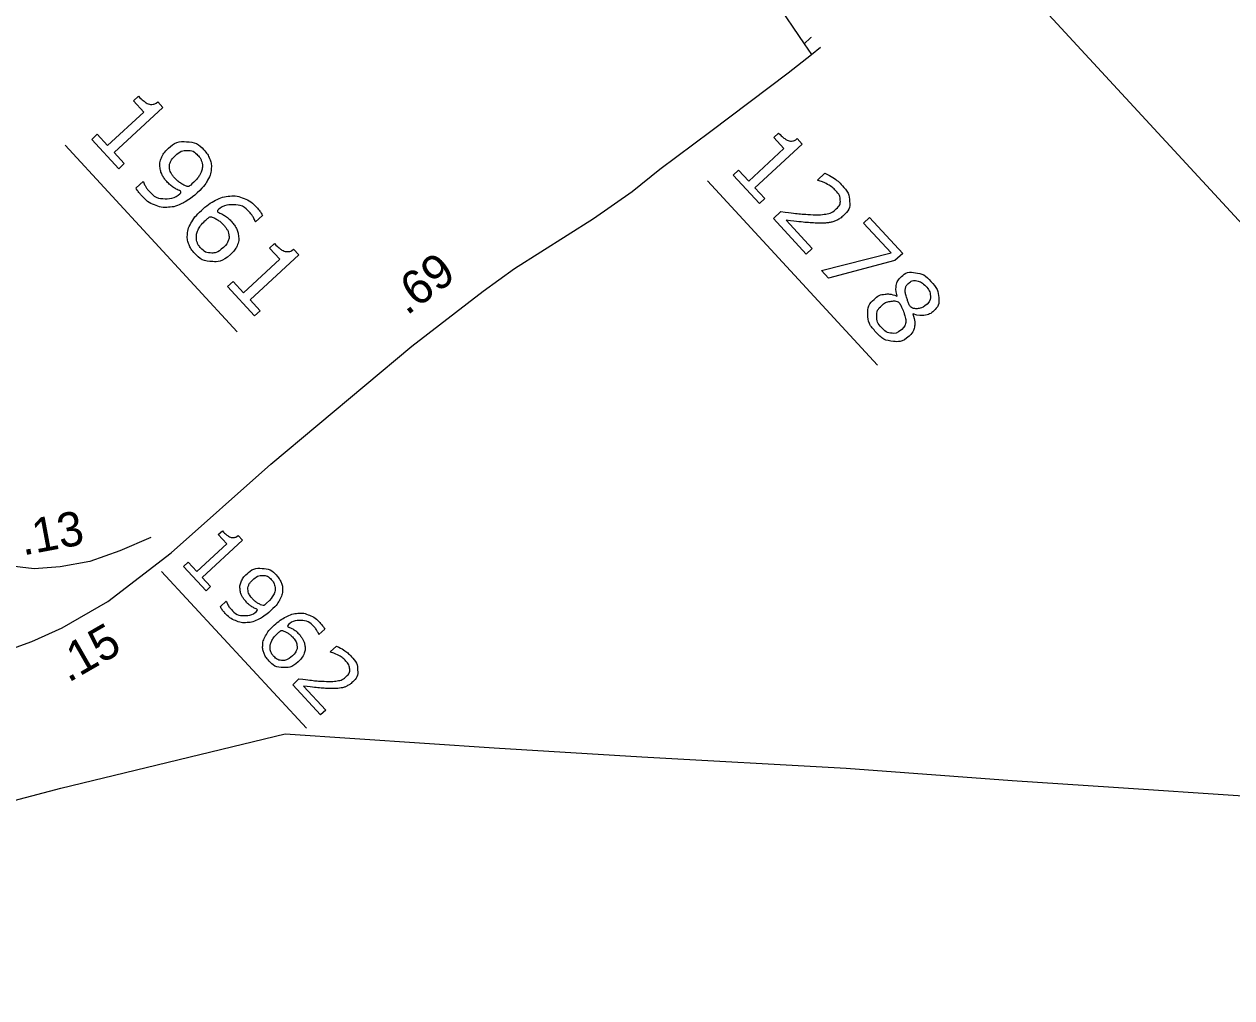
# Model space of a CAD drawing. Extents: x 1695041 to 1706254, y 786537 to 798223.
# Drawn here: x 1703431.2 to 1703634.1, y 796970.9 to 797134.4 of the extents above; entities that cross this region are included whole.
import ezdxf

# ---------------------------------------------------------------- set-up
doc = ezdxf.new("R2010")
doc.units = 0
for name, color, linetype in [('Default', 7, 'Continuous'), ('Old_Level_32', 7, 'Continuous'), ('Sheet Title CELL', 7, 'Continuous')]:
    doc.layers.add(name, color=color, linetype=linetype)

msp = doc.modelspace()

# ---------------------------------------------------------------- linework, layer by layer
at = {"layer": 'Default'}
for p, q in [((1703835.77, 796884.26), (1703207.65, 797564.73)), ((1703438.09, 797114.05), (1703467.03, 797082.7)), ((1703546.02, 797108.1), (1703574.62, 797077.11)), ((1703454.31, 797042.48), (1703478.63, 797016.14))]:
    msp.add_line(p, q, dxfattribs=at)
for points in [[(1703563.46, 797132.18), (1703563.36, 797132.1), (1703562.3, 797131.12)], [(1703563.52, 797129.33), (1703565, 797130.52)], [(1703447.11, 797110.12), (1703442.57, 797115.04), (1703443.5, 797115.9), (1703445.24, 797114), (1703451.34, 797119.63), (1703449.59, 797121.52), (1703450.42, 797122.29)], [(1703453.65, 797121.34), (1703454.53, 797120.4), (1703446.33, 797112.83), (1703448.04, 797110.97), (1703447.11, 797110.12)], [(1703554.77, 797104.28), (1703550.36, 797109.05), (1703551.27, 797109.89), (1703552.96, 797108.05), (1703558.88, 797113.51), (1703557.18, 797115.34), (1703557.99, 797116.09)], [(1703561.12, 797115.17), (1703561.97, 797114.25), (1703554.01, 797106.91), (1703555.67, 797105.11), (1703554.77, 797104.28)], [(1703450.02, 797106.89), (1703451.2, 797107.97), (1703451.25, 797107.91)], [(1703564.58, 797108.14), (1703564.52, 797108.2), (1703565.76, 797109.35)], [(1703471.25, 797102.28), (1703470.07, 797101.2), (1703470.02, 797101.26)], [(1703562.62, 797095.77), (1703557.1, 797101.75), (1703558.35, 797102.91)], [(1703559.26, 797101.47), (1703563.65, 797096.72), (1703562.62, 797095.77)], [(1703577.53, 797094.68), (1703566.34, 797091.74), (1703565.17, 797093.01), (1703576.87, 797095.97), (1703572.24, 797100.98), (1703573.28, 797101.94), (1703578.85, 797095.9), (1703577.53, 797094.68)], [(1703469.94, 797085.38), (1703465.4, 797090.31), (1703466.33, 797091.16), (1703468.07, 797089.27), (1703474.17, 797094.9), (1703472.42, 797096.79), (1703473.25, 797097.56)], [(1703476.48, 797096.61), (1703477.35, 797095.66), (1703469.16, 797088.1), (1703470.87, 797086.24), (1703469.94, 797085.38)], [(1703577.87, 797088.71), (1703577.91, 797088.74)], [(1703580.57, 797085.76), (1703580.53, 797085.73)], [(1703461.77, 797039.23), (1703458.01, 797043.3), (1703458.78, 797044.01), (1703460.23, 797042.44), (1703465.26, 797047.09), (1703463.82, 797048.66), (1703464.51, 797049.29)], [(1703467.17, 797048.51), (1703467.9, 797047.73), (1703461.12, 797041.47), (1703462.54, 797039.94), (1703461.77, 797039.23)], [(1703464.18, 797036.56), (1703465.15, 797037.46), (1703465.19, 797037.41)], [(1703481.71, 797032.75), (1703480.74, 797031.86), (1703480.7, 797031.91)], [(1703482.7, 797028.89), (1703482.65, 797028.95), (1703483.71, 797029.92)], [(1703481.03, 797018.36), (1703476.33, 797023.45), (1703477.39, 797024.44)], [(1703478.17, 797023.21), (1703481.9, 797019.16), (1703481.03, 797018.36)], [(1703291.97, 797015.19), (1703324.69, 797005.69), (1703340.9, 797002.01), (1703346.94, 797000.11), (1703357.14, 796996.22), (1703368.85, 796991.59), (1703392.4, 796995.22), (1703415.7, 797000.36), (1703437.39, 797006.05), (1703475.08, 797015.18), (1703510.21, 797012.82), (1703534.98, 797011.35), (1703569.35, 797009.42), (1703597.22, 797007.38), (1703614.23, 797006.26), (1703657.83, 797003.31), (1703684.12, 797001.47)]]:
    msp.add_lwpolyline(points, dxfattribs=at)
for points in [[(1703450.42, 797122.29), (1703450.78, 797121.91), (1703451.25, 797121.53), (1703451.72, 797121.14), (1703452.05, 797121.03), (1703452.46, 797120.89), (1703452.85, 797120.95), (1703453.23, 797121), (1703453.65, 797121.34)], [(1703557.99, 797116.09), (1703558.33, 797115.72), (1703558.79, 797115.35), (1703559.24, 797114.98), (1703559.56, 797114.87), (1703559.96, 797114.73), (1703560.34, 797114.79), (1703560.71, 797114.84), (1703561.12, 797115.17)], [(1703451.25, 797107.91), (1703451.32, 797107.65), (1703451.54, 797107.25), (1703451.75, 797106.85), (1703452.12, 797106.45), (1703453.37, 797105.1), (1703454.88, 797105.08), (1703456.4, 797105.06), (1703457.93, 797106.25), (1703457.07, 797106.51), (1703456.46, 797106.87), (1703455.85, 797107.24), (1703455.3, 797107.83), (1703454.79, 797108.39), (1703454.48, 797108.94), (1703454.17, 797109.5), (1703454.06, 797110.25), (1703453.94, 797111.13), (1703454.27, 797111.94), (1703454.59, 797112.74), (1703455.39, 797113.48), (1703456.79, 797114.76), (1703458.51, 797114.66), (1703460.23, 797114.55), (1703461.44, 797113.23), (1703462.05, 797112.57), (1703462.37, 797111.82), (1703462.68, 797111.07), (1703462.66, 797110.27), (1703462.63, 797109.28), (1703462.09, 797108.26), (1703461.55, 797107.24), (1703460.29, 797106.07)], [(1703459.41, 797107.56), (1703460.36, 797108.44), (1703460.75, 797109.16), (1703461.15, 797109.89), (1703461.15, 797110.52), (1703461.16, 797111.06), (1703460.98, 797111.5), (1703460.79, 797111.94), (1703460.44, 797112.32), (1703459.63, 797113.2), (1703458.61, 797113.2), (1703457.59, 797113.21), (1703456.59, 797112.29), (1703456.01, 797111.75), (1703455.79, 797111.25), (1703455.58, 797110.74), (1703455.66, 797110.1), (1703455.73, 797109.65), (1703455.97, 797109.26), (1703456.21, 797108.87), (1703456.58, 797108.47), (1703457.02, 797108), (1703457.6, 797107.63), (1703458.18, 797107.26), (1703458.81, 797107.06), (1703458.95, 797107.17), (1703459.08, 797107.27), (1703459.22, 797107.38), (1703459.41, 797107.56)], [(1703558.35, 797102.91), (1703559.46, 797102.78), (1703560.57, 797102.64), (1703561.68, 797102.51), (1703562.71, 797102.45), (1703564.86, 797102.33), (1703565.9, 797102.51), (1703566.94, 797102.68), (1703567.69, 797103.38), (1703568.38, 797104.01), (1703568.35, 797104.82), (1703568.32, 797105.64), (1703567.56, 797106.45), (1703567.06, 797106.99), (1703566.29, 797107.45), (1703565.52, 797107.9), (1703564.58, 797108.14)], [(1703565.76, 797109.35), (1703566.36, 797109.12), (1703567.18, 797108.57), (1703568, 797108.03), (1703568.61, 797107.37), (1703569.86, 797106.01), (1703569.92, 797104.64), (1703569.98, 797103.26), (1703568.86, 797102.23), (1703568.36, 797101.76), (1703567.8, 797101.49), (1703567.25, 797101.21), (1703566.63, 797101.1), (1703566.05, 797100.99), (1703565.41, 797100.98), (1703564.76, 797100.96), (1703563.92, 797101.01), (1703562.71, 797101.07), (1703561.51, 797101.21), (1703560.3, 797101.34), (1703559.26, 797101.47)], [(1703460.29, 797106.07), (1703459.1, 797104.97), (1703457.87, 797104.35), (1703456.65, 797103.72), (1703455.46, 797103.64), (1703454.25, 797103.55), (1703453.09, 797104.04), (1703451.94, 797104.53), (1703450.9, 797105.66), (1703450.61, 797105.97), (1703450.38, 797106.29), (1703450.15, 797106.6), (1703450.02, 797106.89)], [(1703465.88, 797095.7), (1703464.5, 797094.41), (1703462.78, 797094.52), (1703461.06, 797094.62), (1703459.83, 797095.95), (1703459.21, 797096.62), (1703458.91, 797097.36), (1703458.61, 797098.1), (1703458.63, 797098.9), (1703458.66, 797099.9), (1703459.23, 797100.95), (1703459.81, 797102.01), (1703460.99, 797103.1), (1703462.2, 797104.22), (1703463.37, 797104.82), (1703464.55, 797105.42), (1703465.8, 797105.53), (1703466.98, 797105.62), (1703468.16, 797105.13), (1703469.33, 797104.64), (1703470.37, 797103.51), (1703470.7, 797103.15), (1703470.9, 797102.88), (1703471.09, 797102.61), (1703471.25, 797102.28)], [(1703470.02, 797101.26), (1703469.95, 797101.52), (1703469.72, 797101.94), (1703469.48, 797102.36), (1703469.15, 797102.72), (1703467.94, 797104.03), (1703466.4, 797104.06), (1703464.85, 797104.08), (1703463.34, 797102.92), (1703464.12, 797102.69), (1703464.74, 797102.34), (1703465.36, 797102), (1703465.97, 797101.34), (1703466.5, 797100.76), (1703466.8, 797100.22), (1703467.1, 797099.68), (1703467.21, 797098.92), (1703467.33, 797098.04), (1703467.01, 797097.24), (1703466.7, 797096.45), (1703465.88, 797095.7)], [(1703464.68, 797096.89), (1703465.25, 797097.41), (1703465.47, 797097.92), (1703465.69, 797098.43), (1703465.61, 797099.07), (1703465.54, 797099.53), (1703465.29, 797099.93), (1703465.03, 797100.33), (1703464.69, 797100.7), (1703464.21, 797101.22), (1703463.68, 797101.55), (1703463.15, 797101.88), (1703462.46, 797102.11), (1703462.31, 797102), (1703462.18, 797101.89), (1703462.05, 797101.78), (1703461.86, 797101.61), (1703460.9, 797100.72), (1703460.52, 797100.01), (1703460.15, 797099.29), (1703460.14, 797098.65), (1703460.14, 797098.12), (1703460.31, 797097.68), (1703460.49, 797097.24), (1703460.84, 797096.85), (1703461.66, 797095.97), (1703462.67, 797095.96), (1703463.67, 797095.95), (1703464.68, 797096.89)], [(1703473.25, 797097.56), (1703473.61, 797097.17), (1703474.08, 797096.79), (1703474.55, 797096.41), (1703474.88, 797096.3), (1703475.29, 797096.16), (1703475.68, 797096.21), (1703476.06, 797096.27), (1703476.48, 797096.61)], [(1703577.91, 797088.74), (1703577.63, 797089.8), (1703577.77, 797090.56), (1703577.9, 797091.32), (1703578.58, 797091.94), (1703579.57, 797092.86), (1703580.99, 797092.65), (1703582.41, 797092.45), (1703583.58, 797091.18), (1703584.8, 797089.86), (1703584.89, 797088.49), (1703584.99, 797087.11), (1703584.01, 797086.21), (1703583.41, 797085.66), (1703582.49, 797085.5), (1703581.56, 797085.34), (1703580.57, 797085.76)], [(1703582.92, 797087.37), (1703583.55, 797087.95), (1703583.48, 797088.79), (1703583.4, 797089.63), (1703582.7, 797090.39), (1703582.01, 797091.13), (1703581.21, 797091.28), (1703580.42, 797091.43), (1703579.81, 797090.88), (1703579.38, 797090.48), (1703579.3, 797089.95), (1703579.21, 797089.43), (1703579.41, 797088.72), (1703579.51, 797088.4), (1703579.72, 797087.83), (1703579.93, 797087.26), (1703580.18, 797086.76), (1703581.11, 797086.53), (1703581.74, 797086.7), (1703582.37, 797086.86), (1703582.92, 797087.37)], [(1703579.91, 797081.98), (1703578.76, 797080.93), (1703577.18, 797081.12), (1703575.6, 797081.31), (1703574.35, 797082.67), (1703573.02, 797084.1), (1703572.98, 797085.64), (1703572.94, 797087.17), (1703574.09, 797088.24), (1703574.83, 797088.92), (1703575.82, 797089.04), (1703576.81, 797089.16), (1703577.87, 797088.71)], [(1703578.67, 797083.1), (1703579.22, 797083.6), (1703579.32, 797084.15), (1703579.43, 797084.69), (1703579.12, 797085.7), (1703578.99, 797086.1), (1703578.79, 797086.53), (1703578.6, 797086.97), (1703578.29, 797087.71), (1703577.51, 797087.97), (1703576.72, 797087.83), (1703575.92, 797087.7), (1703575.29, 797087.12), (1703574.49, 797086.38), (1703574.48, 797085.35), (1703574.47, 797084.31), (1703575.25, 797083.47), (1703576.05, 797082.6), (1703576.97, 797082.49), (1703577.9, 797082.38), (1703578.67, 797083.1)], [(1703580.53, 797085.73), (1703580.95, 797084.57), (1703580.83, 797083.65), (1703580.71, 797082.73), (1703579.91, 797081.98)], [(1703464.51, 797049.29), (1703464.8, 797048.97), (1703465.19, 797048.66), (1703465.58, 797048.34), (1703465.85, 797048.25), (1703466.19, 797048.13), (1703466.51, 797048.18), (1703466.83, 797048.23), (1703467.17, 797048.51)], [(1703465.19, 797037.41), (1703465.25, 797037.19), (1703465.43, 797036.86), (1703465.61, 797036.53), (1703465.91, 797036.2), (1703466.94, 797035.08), (1703468.19, 797035.07), (1703469.44, 797035.05), (1703470.71, 797036.04), (1703470, 797036.25), (1703469.49, 797036.55), (1703468.99, 797036.85), (1703468.54, 797037.34), (1703468.11, 797037.8), (1703467.86, 797038.26), (1703467.6, 797038.72), (1703467.51, 797039.34), (1703467.41, 797040.07), (1703467.68, 797040.73), (1703467.95, 797041.4), (1703468.61, 797042.01), (1703469.76, 797043.07), (1703471.19, 797042.98), (1703472.61, 797042.89), (1703473.61, 797041.8), (1703474.12, 797041.26), (1703474.38, 797040.64), (1703474.64, 797040.01), (1703474.62, 797039.35), (1703474.6, 797038.54), (1703474.15, 797037.7), (1703473.71, 797036.85), (1703472.66, 797035.89)], [(1703471.93, 797037.12), (1703472.72, 797037.84), (1703473.04, 797038.44), (1703473.37, 797039.04), (1703473.37, 797039.56), (1703473.38, 797040.01), (1703473.23, 797040.37), (1703473.07, 797040.74), (1703472.78, 797041.05), (1703472.11, 797041.78), (1703471.27, 797041.78), (1703470.42, 797041.78), (1703469.6, 797041.02), (1703469.12, 797040.58), (1703468.94, 797040.16), (1703468.77, 797039.75), (1703468.84, 797039.22), (1703468.89, 797038.84), (1703469.09, 797038.52), (1703469.29, 797038.2), (1703469.59, 797037.87), (1703469.96, 797037.48), (1703470.43, 797037.17), (1703470.91, 797036.87), (1703471.44, 797036.7), (1703471.55, 797036.79), (1703471.66, 797036.88), (1703471.77, 797036.97), (1703471.93, 797037.12)], [(1703472.66, 797035.89), (1703471.67, 797034.98), (1703470.66, 797034.46), (1703469.65, 797033.95), (1703468.67, 797033.88), (1703467.66, 797033.8), (1703466.71, 797034.21), (1703465.76, 797034.61), (1703464.9, 797035.54), (1703464.66, 797035.81), (1703464.47, 797036.06), (1703464.28, 797036.32), (1703464.18, 797036.56)], [(1703477.28, 797027.31), (1703476.14, 797026.25), (1703474.71, 797026.34), (1703473.29, 797026.42), (1703472.28, 797027.52), (1703471.77, 797028.08), (1703471.52, 797028.69), (1703471.27, 797029.3), (1703471.29, 797029.96), (1703471.31, 797030.78), (1703471.79, 797031.66), (1703472.26, 797032.53), (1703473.24, 797033.43), (1703474.24, 797034.35), (1703475.21, 797034.85), (1703476.18, 797035.35), (1703477.21, 797035.44), (1703478.19, 797035.52), (1703479.16, 797035.11), (1703480.13, 797034.71), (1703480.99, 797033.77), (1703481.27, 797033.47), (1703481.43, 797033.25), (1703481.59, 797033.02), (1703481.71, 797032.75)], [(1703476.29, 797028.3), (1703476.76, 797028.73), (1703476.94, 797029.15), (1703477.12, 797029.57), (1703477.05, 797030.1), (1703477, 797030.48), (1703476.79, 797030.81), (1703476.58, 797031.14), (1703476.3, 797031.45), (1703475.9, 797031.87), (1703475.46, 797032.15), (1703475.02, 797032.42), (1703474.45, 797032.62), (1703474.33, 797032.52), (1703474.22, 797032.43), (1703474.11, 797032.34), (1703473.96, 797032.2), (1703473.16, 797031.46), (1703472.85, 797030.87), (1703472.54, 797030.28), (1703472.54, 797029.75), (1703472.53, 797029.31), (1703472.68, 797028.95), (1703472.82, 797028.58), (1703473.12, 797028.27), (1703473.79, 797027.54), (1703474.62, 797027.53), (1703475.46, 797027.52), (1703476.29, 797028.3)], [(1703480.7, 797031.91), (1703480.64, 797032.12), (1703480.45, 797032.47), (1703480.26, 797032.82), (1703479.98, 797033.12), (1703478.98, 797034.2), (1703477.71, 797034.22), (1703476.43, 797034.24), (1703475.18, 797033.28), (1703475.83, 797033.09), (1703476.34, 797032.81), (1703476.85, 797032.52), (1703477.35, 797031.98), (1703477.79, 797031.5), (1703478.04, 797031.05), (1703478.29, 797030.6), (1703478.38, 797029.97), (1703478.48, 797029.25), (1703478.22, 797028.59), (1703477.95, 797027.93), (1703477.28, 797027.31)], [(1703477.39, 797024.44), (1703478.34, 797024.32), (1703479.29, 797024.21), (1703480.23, 797024.09), (1703481.11, 797024.05), (1703482.94, 797023.94), (1703483.83, 797024.09), (1703484.71, 797024.24), (1703485.35, 797024.84), (1703485.94, 797025.38), (1703485.91, 797026.07), (1703485.88, 797026.76), (1703485.24, 797027.45), (1703484.82, 797027.92), (1703484.16, 797028.3), (1703483.5, 797028.69), (1703482.7, 797028.89)], [(1703483.71, 797029.92), (1703484.22, 797029.73), (1703484.92, 797029.26), (1703485.62, 797028.8), (1703486.13, 797028.24), (1703487.2, 797027.08), (1703487.25, 797025.91), (1703487.3, 797024.74), (1703486.35, 797023.86), (1703485.92, 797023.46), (1703485.45, 797023.23), (1703484.98, 797022.99), (1703484.45, 797022.9), (1703483.95, 797022.81), (1703483.41, 797022.79), (1703482.86, 797022.78), (1703482.14, 797022.82), (1703481.11, 797022.87), (1703480.08, 797022.99), (1703479.05, 797023.1), (1703478.17, 797023.21)]]:
    msp.add_open_spline(points, degree=3, dxfattribs=at)
at = {"layer": 'Old_Level_32'}
for points in [[(1703553.78, 797142.67), (1703557.42, 797138.26), (1703562.3, 797131.12)], [(1703562.3, 797131.12), (1703563.52, 797129.33)], [(1703455.9, 797045.61), (1703472.64, 797060.47), (1703496.35, 797080.33), (1703508.34, 797089.56), (1703513.59, 797093.34), (1703526.87, 797101.76), (1703533.39, 797106.3), (1703538, 797110.02), (1703546.61, 797116.44), (1703559.57, 797126.21), (1703563.52, 797129.33)], [(1703452.49, 797048.19), (1703447.3, 797045.95), (1703442.26, 797044.17), (1703437.25, 797043.23), (1703432.91, 797042.91), (1703428.18, 797043.46), (1703422.68, 797044.39)], [(1703420.61, 797027.76), (1703427.23, 797028.83), (1703432.5, 797030.72), (1703437.57, 797033.01), (1703445.26, 797037.42), (1703455.9, 797045.61)]]:
    msp.add_lwpolyline(points, dxfattribs=at)

# ---------------------------------------------------------------- texts
at = {"layer": 'Default'}
for s, height, rotation, p in [('Norfolk', 14.412, 233.877, (1703436.71, 797183.16)), ('.69', 5.775, 36.7746, (1703495.5, 797085.37)), ('.13', 5.775, 10.5685, (1703431.01, 797045.14)), ('.15', 5.775, 29.8823, (1703438.62, 797023.72))]:
    msp.add_text(s, height=height, rotation=rotation, dxfattribs=at).set_placement(p)
at = {"layer": 'Sheet Title CELL'}
msp.add_text('See Sheet 1-A For Index of Sheets', height=22.5, rotation=312.7091, dxfattribs=at).set_placement((1703379.74, 797426.2))

doc.saveas('drawing.dxf')
